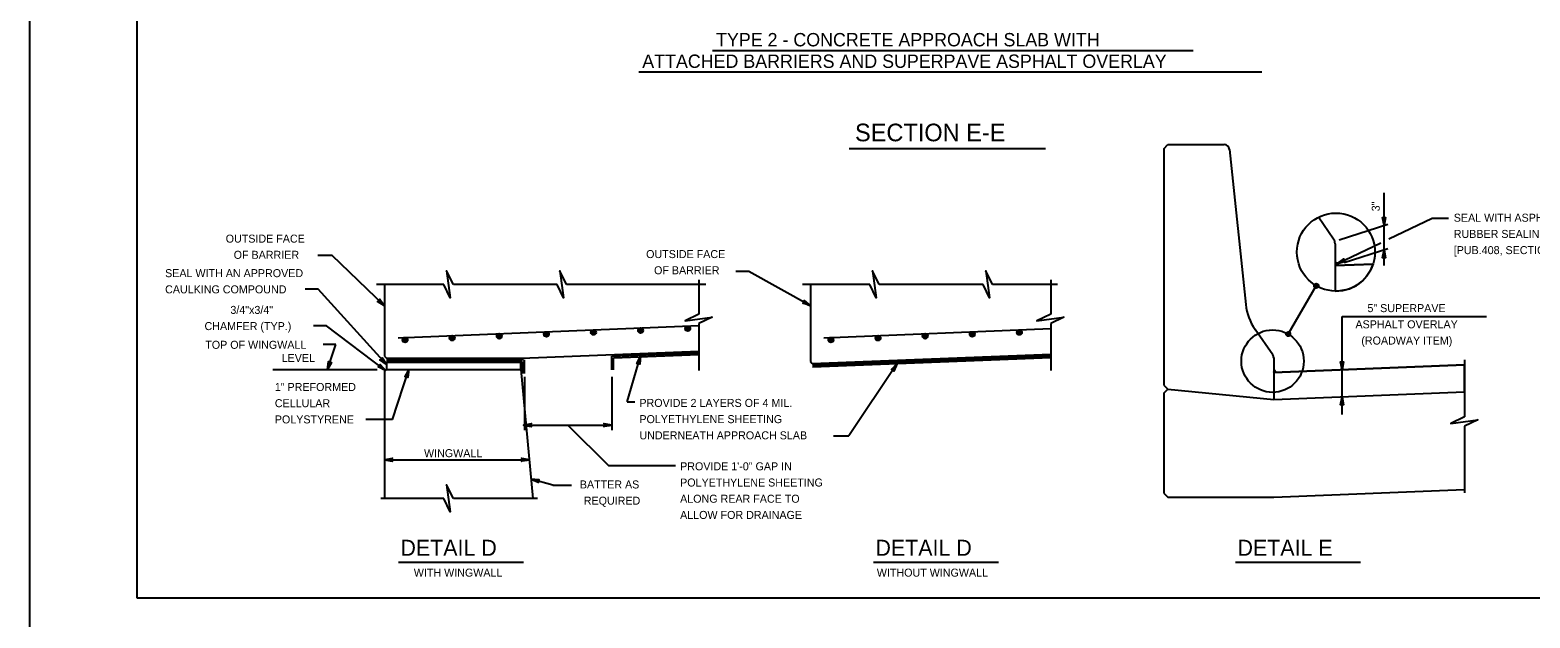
# Model space of a CAD drawing. Extents: x 636530 to 644067, y 294168 to 299122.
# Drawn here: x 638166 to 638728, y 297146 to 297366 of the extents above; entities that cross this region are included whole.
import ezdxf

# ---------------------------------------------------------------- set-up
doc = ezdxf.new("R2010")
doc.units = 0
doc.layers.add('1', color=7, linetype='Continuous')
doc.layers.add('PLT-BNDY', color=7, linetype='Continuous')

msp = doc.modelspace()

# ---------------------------------------------------------------- linework, layer by layer
at = {"layer": '1'}
for p, q in [((638205.78, 297717.48), (638205.78, 297153.48)), ((638421.64, 297358.59), (638601.78, 297358.59)), ((638393.93, 297350.66), (638627.46, 297350.66)), ((638472.78, 297321.93), (638546.37, 297321.93)), ((638590.8, 297321.82), (638592.32, 297323.35)), ((638590.8, 297321.82), (638590.8, 297233.27)), ((638592.32, 297323.35), (638613.36, 297323.35)), ((638615.38, 297321.53), (638621.5, 297263.45)), ((638673.29, 297278.03), (638673.29, 297305.33)), ((638654.39, 297287.97), (638648.7, 297296.14)), ((638656.53, 297287.69), (638674.72, 297293.57)), ((638675.11, 297288), (638691.29, 297295.75)), ((638691.29, 297295.75), (638697.47, 297295.75)), ((638654.94, 297286.22), (638654.94, 297268.45)), ((638655.83, 297278.75), (638672.05, 297286.53)), ((638279.01, 297281.84), (638273.63, 297281.84)), ((638298.63, 297262.95), (638279.01, 297281.84)), ((638658.37, 297279.14), (638674.72, 297284.42)), ((638435.25, 297275.84), (638430.38, 297275.84)), ((638458.27, 297262.95), (638435.25, 297275.84)), ((638654.94, 297278.04), (638669.21, 297278.61)), ((638273.74, 297269.19), (638268.87, 297269.19)), ((638299.39, 297240.9), (638273.74, 297269.19)), ((638320.95, 297270.92), (638295.64, 297270.92)), ((638298.63, 297270.92), (638298.63, 297244.08)), ((638363.41, 297270.92), (638324.47, 297270.92)), ((638419.05, 297270.92), (638366.93, 297270.92)), ((638416.49, 297272.73), (638416.49, 297259.8)), ((638480.6, 297270.92), (638455.29, 297270.92)), ((638458.27, 297270.92), (638458.27, 297242.02)), ((638523.06, 297270.92), (638484.12, 297270.92)), ((638550.92, 297270.92), (638526.57, 297270.92)), ((638548.35, 297272.73), (638548.35, 297259.8)), ((638637.38, 297252.34), (638647.92, 297270.44)), ((638657.56, 297222.25), (638657.56, 297258.96)), ((638657.56, 297258.96), (638711.74, 297258.96)), ((638276.86, 297255.42), (638271.99, 297255.42)), ((638299.04, 297238.72), (638276.86, 297255.42)), ((638303.73, 297251), (638416.49, 297255.51)), ((638416.49, 297256.28), (638416.49, 297238.65)), ((638463.38, 297251), (638548.35, 297254.4)), ((638548.35, 297256.28), (638548.35, 297238.65)), ((638631.58, 297244.62), (638624.99, 297254.09)), ((638280.36, 297248.46), (638275.73, 297248.46)), ((638277.29, 297239.07), (638280.36, 297248.46)), ((638350.06, 297243.32), (638416.49, 297245.98)), ((638298.63, 297244.08), (638299.39, 297243.32)), ((638299.39, 297243.32), (638350.06, 297243.32)), ((638350.81, 297242.68), (638299.39, 297242.68)), ((638350.18, 297242.05), (638299.39, 297242.05)), ((638350.34, 297237.63), (638350.34, 297242.05)), ((638351.11, 297237.63), (638351.11, 297242.68)), ((638383.88, 297244.04), (638416.49, 297245.34)), ((638383.88, 297238.98), (638383.88, 297244.04)), ((638384.51, 297243.43), (638416.49, 297244.71)), ((638384.51, 297238.98), (638384.51, 297243.43)), ((638389.59, 297226.92), (638394.62, 297244.06)), ((638458.27, 297242.02), (638459.01, 297241.29)), ((638459.01, 297241.29), (638548.35, 297244.86)), ((638459.03, 297240.66), (638548.35, 297244.23)), ((638459.06, 297240.02), (638548.35, 297243.6)), ((638490.76, 297241.29), (638472.74, 297214.18)), ((638631.95, 297243.46), (638631.95, 297227.83)), ((638631.95, 297238), (638703.47, 297240.86)), ((638703.47, 297242.73), (638703.47, 297221.38)), ((638703.47, 297230.7), (638703.47, 297240.86)), ((638256.85, 297239.07), (638295.91, 297239.07)), ((638298.63, 297238.31), (638299.39, 297239.07)), ((638298.63, 297238.31), (638298.63, 297190.69)), ((638299.39, 297239.07), (638349.78, 297239.07)), ((638301.68, 297220.35), (638307.8, 297239.07)), ((638349.78, 297239.07), (638354.24, 297190.69)), ((638351.11, 297236.38), (638351.11, 297216.41)), ((638383.88, 297236.38), (638383.88, 297216.41)), ((638590.8, 297233.27), (638592.32, 297231.75)), ((638590.8, 297230.22), (638592.32, 297231.75)), ((638590.8, 297230.22), (638590.8, 297192.75)), ((638592.32, 297231.75), (638631.95, 297227.83)), ((638631.95, 297227.83), (638703.47, 297230.69)), ((638389.59, 297226.92), (638392.46, 297226.92)), ((638301.68, 297220.35), (638291.66, 297220.35)), ((638350.81, 297218.23), (638383.88, 297218.23)), ((638367.34, 297218.23), (638382.64, 297203.17)), ((638703.47, 297217.86), (638703.47, 297192.83)), ((638466.97, 297214.18), (638472.74, 297214.18)), ((638298.63, 297205.27), (638353.02, 297205.27)), ((638382.64, 297203.17), (638407.72, 297203.17)), ((638361.75, 297195.78), (638353.63, 297198.05)), ((638361.75, 297195.78), (638368.73, 297195.78)), ((638320.95, 297190.69), (638297.29, 297190.69)), ((638356.03, 297190.69), (638324.47, 297190.69)), ((638590.8, 297192.75), (638592.32, 297191.23)), ((638592.32, 297191.23), (638631.95, 297191.23)), ((638631.95, 297191.23), (638703.47, 297194.09)), ((638303.9, 297166.88), (638350.7, 297166.88)), ((638481.94, 297166.88), (638528.75, 297166.88)), ((638617.62, 297166.88), (638664.43, 297166.88)), ((638205.78, 297153.48), (638991.78, 297153.48))]:
    msp.add_line(p, q, dxfattribs=at)
for points in [[(638673.29, 297293.1), (638672.73, 297296.09), (638672.89, 297295.86), (638673.09, 297295.74), (638673.29, 297295.7), (638673.49, 297295.74), (638673.69, 297295.86), (638673.84, 297296.09), (638673.29, 297293.1), (638673.69, 297295.86), (638673.49, 297295.74), (638673.29, 297293.1), (638673.29, 297295.7), (638673.09, 297295.74), (638673.29, 297293.1), (638672.89, 297295.86)], [(638655.83, 297278.75), (638658.28, 297280.55), (638658.14, 297280.3), (638658.12, 297280.07), (638658.18, 297279.88), (638658.29, 297279.71), (638658.49, 297279.58), (638658.76, 297279.54), (638655.83, 297278.75), (638658.49, 297279.58), (638658.29, 297279.71), (638655.83, 297278.75), (638658.18, 297279.88), (638658.12, 297280.07), (638655.83, 297278.75), (638658.14, 297280.3)], [(638673.29, 297283.96), (638673.84, 297280.98), (638673.69, 297281.21), (638673.49, 297281.33), (638673.29, 297281.36), (638673.09, 297281.33), (638672.89, 297281.21), (638672.73, 297280.98), (638673.29, 297283.96), (638672.89, 297281.21), (638673.09, 297281.33), (638673.29, 297283.96), (638673.29, 297281.36), (638673.49, 297281.33), (638673.29, 297283.96), (638673.69, 297281.21)], [(638324.47, 297270.92), (638321.93, 297276.11), (638323.31, 297265.96), (638320.95, 297270.92)], [(638366.93, 297270.92), (638364.39, 297276.11), (638365.77, 297265.96), (638363.41, 297270.92)], [(638484.12, 297270.92), (638481.58, 297276.11), (638482.96, 297265.96), (638480.6, 297270.92)], [(638526.57, 297270.92), (638524.04, 297276.11), (638525.42, 297265.96), (638523.06, 297270.92)], [(638654.94, 297268.45), (638657.87, 297268.68), (638660.35, 297269.35), (638662.94, 297270.61), (638665.05, 297272.19), (638666.9, 297274.18), (638668.32, 297276.43), (638669.21, 297278.61)], [(638669.21, 297278.61), (638654.94, 297278.04), (638654.94, 297268.45)], [(638298.63, 297262.95), (638296.09, 297264.62), (638296.37, 297264.57), (638296.59, 297264.64), (638296.76, 297264.76), (638296.87, 297264.92), (638296.92, 297265.15), (638296.87, 297265.42), (638298.63, 297262.95), (638296.92, 297265.15), (638296.87, 297264.92), (638298.63, 297262.95), (638296.76, 297264.76), (638296.59, 297264.64), (638298.63, 297262.95), (638296.37, 297264.57)], [(638458.27, 297262.95), (638455.4, 297263.92), (638455.68, 297263.95), (638455.88, 297264.07), (638456.01, 297264.22), (638456.07, 297264.41), (638456.07, 297264.65), (638455.94, 297264.9), (638458.27, 297262.95), (638456.07, 297264.65), (638456.07, 297264.41), (638458.27, 297262.95), (638456.01, 297264.22), (638455.88, 297264.07), (638458.27, 297262.95), (638455.68, 297263.95)], [(638416.49, 297259.8), (638411.3, 297257.26), (638421.45, 297258.64), (638416.49, 297256.28)], [(638548.35, 297259.8), (638543.17, 297257.26), (638553.32, 297258.64), (638548.35, 297256.28)], [(638277.29, 297239.07), (638277.69, 297242.08), (638277.73, 297241.94), (638277.77, 297241.81), (638277.84, 297241.72), (638277.92, 297241.64), (638278.01, 297241.59), (638278.1, 297241.54), (638278.2, 297241.53), (638278.3, 297241.51), (638278.41, 297241.54), (638278.53, 297241.56), (638278.64, 297241.65), (638278.75, 297241.73), (638277.29, 297239.07), (638278.64, 297241.65), (638278.53, 297241.56), (638277.29, 297239.07), (638278.41, 297241.54), (638278.3, 297241.51), (638277.29, 297239.07), (638278.2, 297241.53), (638278.1, 297241.54), (638277.29, 297239.07), (638278.01, 297241.59), (638277.92, 297241.64), (638277.29, 297239.07), (638277.84, 297241.72), (638277.77, 297241.81), (638277.29, 297239.07), (638277.73, 297241.94)], [(638299.04, 297238.72), (638296.32, 297240.06), (638296.46, 297240.06), (638296.6, 297240.05), (638296.71, 297240.1), (638296.81, 297240.14), (638296.89, 297240.21), (638296.96, 297240.28), (638297.01, 297240.37), (638297.05, 297240.46), (638297.07, 297240.58), (638297.08, 297240.69), (638297.04, 297240.82), (638296.99, 297240.96), (638299.04, 297238.72), (638297.04, 297240.82), (638297.08, 297240.69), (638299.04, 297238.72), (638297.07, 297240.58), (638297.05, 297240.46), (638299.04, 297238.72), (638297.01, 297240.37), (638296.96, 297240.28), (638299.04, 297238.72), (638296.89, 297240.21), (638296.81, 297240.14), (638299.04, 297238.72), (638296.71, 297240.1), (638296.6, 297240.05), (638299.04, 297238.72), (638296.46, 297240.06)], [(638299.39, 297240.9), (638296.97, 297242.73), (638297.11, 297242.7), (638297.25, 297242.67), (638297.36, 297242.69), (638297.47, 297242.72), (638297.56, 297242.77), (638297.64, 297242.82), (638297.71, 297242.9), (638297.77, 297242.98), (638297.8, 297243.1), (638297.84, 297243.21), (638297.82, 297243.35), (638297.8, 297243.48), (638299.39, 297240.9), (638297.82, 297243.35), (638297.84, 297243.21), (638299.39, 297240.9), (638297.8, 297243.1), (638297.77, 297242.98), (638299.39, 297240.9), (638297.71, 297242.9), (638297.64, 297242.82), (638299.39, 297240.9), (638297.56, 297242.77), (638297.47, 297242.72), (638299.39, 297240.9), (638297.36, 297242.69), (638297.25, 297242.67), (638299.39, 297240.9), (638297.11, 297242.7)], [(638394.62, 297244.06), (638394.31, 297241.04), (638394.23, 297241.3), (638394.07, 297241.47), (638393.88, 297241.56), (638393.68, 297241.59), (638393.46, 297241.53), (638393.24, 297241.35), (638394.62, 297244.06), (638393.46, 297241.53), (638393.68, 297241.59), (638394.62, 297244.06), (638393.88, 297241.56), (638394.07, 297241.47), (638394.62, 297244.06), (638394.23, 297241.3)], [(638490.76, 297241.29), (638489.57, 297238.5), (638489.57, 297238.78), (638489.46, 297238.99), (638489.32, 297239.13), (638489.13, 297239.21), (638488.9, 297239.22), (638488.64, 297239.12), (638490.76, 297241.29), (638488.9, 297239.22), (638489.13, 297239.21), (638490.76, 297241.29), (638489.32, 297239.13), (638489.46, 297238.99), (638490.76, 297241.29), (638489.57, 297238.78)], [(638703.47, 297240.86), (638631.95, 297238), (638631.95, 297227.84), (638703.47, 297230.7)], [(638657.56, 297239.03), (638657.01, 297242.01), (638657.08, 297241.89), (638657.16, 297241.78), (638657.26, 297241.72), (638657.36, 297241.66), (638657.46, 297241.64), (638657.56, 297241.63), (638657.66, 297241.64), (638657.76, 297241.66), (638657.86, 297241.72), (638657.96, 297241.78), (638658.04, 297241.89), (638658.12, 297242.01), (638657.56, 297239.03), (638658.04, 297241.89), (638657.96, 297241.78), (638657.56, 297239.03), (638657.86, 297241.72), (638657.76, 297241.66), (638657.56, 297239.03), (638657.66, 297241.64), (638657.56, 297241.63), (638657.56, 297239.03), (638657.46, 297241.64), (638657.36, 297241.66), (638657.56, 297239.03), (638657.26, 297241.72), (638657.16, 297241.78), (638657.56, 297239.03), (638657.08, 297241.89)], [(638307.8, 297239.07), (638306.34, 297236.41), (638306.46, 297236.49), (638306.57, 297236.58), (638306.68, 297236.6), (638306.79, 297236.63), (638306.89, 297236.61), (638307, 297236.6), (638307.08, 297236.55), (638307.17, 297236.5), (638307.25, 297236.42), (638307.33, 297236.33), (638307.37, 297236.19), (638307.41, 297236.06), (638307.8, 297239.07), (638307.37, 297236.19), (638307.33, 297236.33), (638307.8, 297239.07), (638307.25, 297236.42), (638307.17, 297236.5), (638307.8, 297239.07), (638307.08, 297236.55), (638307, 297236.6), (638307.8, 297239.07), (638306.89, 297236.61), (638306.79, 297236.63), (638307.8, 297239.07), (638306.68, 297236.6), (638306.57, 297236.58), (638307.8, 297239.07), (638306.46, 297236.49)], [(638657.56, 297228.86), (638658.12, 297225.87), (638658.04, 297225.99), (638657.96, 297226.1), (638657.86, 297226.16), (638657.76, 297226.22), (638657.66, 297226.24), (638657.56, 297226.26), (638657.46, 297226.24), (638657.36, 297226.22), (638657.26, 297226.16), (638657.16, 297226.1), (638657.08, 297225.99), (638657.01, 297225.87), (638657.56, 297228.86), (638657.08, 297225.99), (638657.16, 297226.1), (638657.56, 297228.86), (638657.26, 297226.16), (638657.36, 297226.22), (638657.56, 297228.86), (638657.46, 297226.24), (638657.56, 297226.26), (638657.56, 297228.86), (638657.66, 297226.24), (638657.76, 297226.22), (638657.56, 297228.86), (638657.86, 297226.16), (638657.96, 297226.1), (638657.56, 297228.86), (638658.04, 297225.99)], [(638350.81, 297218.23), (638353.79, 297218.79), (638353.68, 297218.71), (638353.56, 297218.63), (638353.5, 297218.53), (638353.44, 297218.43), (638353.43, 297218.33), (638353.41, 297218.23), (638353.43, 297218.13), (638353.44, 297218.03), (638353.5, 297217.93), (638353.56, 297217.83), (638353.68, 297217.75), (638353.79, 297217.67), (638350.81, 297218.23), (638353.68, 297217.75), (638353.56, 297217.83), (638350.81, 297218.23), (638353.5, 297217.93), (638353.44, 297218.03), (638350.81, 297218.23), (638353.43, 297218.13), (638353.41, 297218.23), (638350.81, 297218.23), (638353.43, 297218.33), (638353.44, 297218.43), (638350.81, 297218.23), (638353.5, 297218.53), (638353.56, 297218.63), (638350.81, 297218.23), (638353.68, 297218.71)], [(638383.88, 297218.23), (638380.9, 297217.67), (638381.01, 297217.75), (638381.13, 297217.83), (638381.19, 297217.93), (638381.24, 297218.03), (638381.26, 297218.13), (638381.28, 297218.23), (638381.26, 297218.33), (638381.24, 297218.43), (638381.19, 297218.53), (638381.13, 297218.63), (638381.01, 297218.71), (638380.9, 297218.79), (638383.88, 297218.23), (638381.01, 297218.71), (638381.13, 297218.63), (638383.88, 297218.23), (638381.19, 297218.53), (638381.24, 297218.43), (638383.88, 297218.23), (638381.26, 297218.33), (638381.28, 297218.23), (638383.88, 297218.23), (638381.26, 297218.13), (638381.24, 297218.03), (638383.88, 297218.23), (638381.19, 297217.93), (638381.13, 297217.83), (638383.88, 297218.23), (638381.01, 297217.75)], [(638703.47, 297221.38), (638698.29, 297218.84), (638708.43, 297220.22), (638703.47, 297217.86)], [(638298.63, 297205.27), (638301.61, 297205.83), (638301.5, 297205.75), (638301.38, 297205.67), (638301.32, 297205.57), (638301.26, 297205.47), (638301.25, 297205.37), (638301.23, 297205.27), (638301.25, 297205.17), (638301.26, 297205.07), (638301.32, 297204.97), (638301.38, 297204.87), (638301.5, 297204.79), (638301.61, 297204.71), (638298.63, 297205.27), (638301.5, 297204.79), (638301.38, 297204.87), (638298.63, 297205.27), (638301.32, 297204.97), (638301.26, 297205.07), (638298.63, 297205.27), (638301.25, 297205.17), (638301.23, 297205.27), (638298.63, 297205.27), (638301.25, 297205.37), (638301.26, 297205.47), (638298.63, 297205.27), (638301.32, 297205.57), (638301.38, 297205.67), (638298.63, 297205.27), (638301.5, 297205.75)], [(638353.02, 297205.27), (638350.04, 297204.71), (638350.16, 297204.79), (638350.27, 297204.87), (638350.33, 297204.97), (638350.39, 297205.07), (638350.41, 297205.17), (638350.42, 297205.27), (638350.41, 297205.37), (638350.39, 297205.47), (638350.33, 297205.57), (638350.27, 297205.67), (638350.16, 297205.75), (638350.04, 297205.83), (638353.02, 297205.27), (638350.16, 297205.75), (638350.27, 297205.67), (638353.02, 297205.27), (638350.33, 297205.57), (638350.39, 297205.47), (638353.02, 297205.27), (638350.41, 297205.37), (638350.42, 297205.27), (638353.02, 297205.27), (638350.41, 297205.17), (638350.39, 297205.07), (638353.02, 297205.27), (638350.33, 297204.97), (638350.27, 297204.87), (638353.02, 297205.27), (638350.16, 297204.79)], [(638324.47, 297190.69), (638321.93, 297195.88), (638323.31, 297185.73), (638320.95, 297190.69)], [(638353.63, 297198.05), (638356.65, 297197.79), (638356.52, 297197.74), (638356.38, 297197.7), (638356.3, 297197.61), (638356.22, 297197.53), (638356.17, 297197.44), (638356.13, 297197.35), (638356.12, 297197.25), (638356.11, 297197.15), (638356.14, 297197.04), (638356.17, 297196.92), (638356.26, 297196.82), (638356.35, 297196.71), (638353.63, 297198.05), (638356.26, 297196.82), (638356.17, 297196.92), (638353.63, 297198.05), (638356.14, 297197.04), (638356.11, 297197.15), (638353.63, 297198.05), (638356.12, 297197.25), (638356.13, 297197.35), (638353.63, 297198.05), (638356.17, 297197.44), (638356.22, 297197.53), (638353.63, 297198.05), (638356.3, 297197.61), (638356.38, 297197.7), (638353.63, 297198.05), (638356.52, 297197.74)]]:
    msp.add_lwpolyline(points, dxfattribs=at)
msp.add_lwpolyline([(638299.39, 297239.07), (638349.78, 297239.07), (638349.78, 297241.67), (638299.39, 297241.67)], close=True, dxfattribs=at)
for centre, radius in [((638655.28, 297283.08), 14.63), ((638647.92, 297270.44), 0.834), ((638306.35, 297250.15), 0.952), ((638324.01, 297250.86), 0.952), ((638324.01, 297250.86), 0.714), ((638324.01, 297250.86), 0.476), ((638324.01, 297250.86), 0.238), ((638341.67, 297251.56), 0.952), ((638341.67, 297251.56), 0.714), ((638341.67, 297251.56), 0.476), ((638341.67, 297251.56), 0.238), ((638359.33, 297252.27), 0.952), ((638359.33, 297252.27), 0.714), ((638359.33, 297252.27), 0.476), ((638359.33, 297252.27), 0.238), ((638376.99, 297252.98), 0.952), ((638376.99, 297252.98), 0.714), ((638376.99, 297252.98), 0.476), ((638376.99, 297252.98), 0.238), ((638394.65, 297253.68), 0.952), ((638394.65, 297253.68), 0.714), ((638394.65, 297253.68), 0.476), ((638394.65, 297253.68), 0.238), ((638412.31, 297254.39), 0.952), ((638412.31, 297254.39), 0.714), ((638412.31, 297254.39), 0.476), ((638412.31, 297254.39), 0.238), ((638466, 297250.15), 0.952), ((638483.66, 297250.86), 0.952), ((638483.66, 297250.86), 0.714), ((638483.66, 297250.86), 0.476), ((638483.66, 297250.86), 0.238), ((638501.32, 297251.56), 0.952), ((638501.32, 297251.56), 0.714), ((638501.32, 297251.56), 0.476), ((638501.32, 297251.56), 0.238), ((638518.98, 297252.27), 0.952), ((638518.98, 297252.27), 0.714), ((638518.98, 297252.27), 0.476), ((638518.98, 297252.27), 0.238), ((638536.64, 297252.98), 0.952), ((638536.64, 297252.98), 0.714), ((638536.64, 297252.98), 0.476), ((638536.64, 297252.98), 0.238), ((638631.52, 297242.21), 11.7), ((638637.38, 297252.34), 0.8), ((638306.35, 297250.15), 0.714), ((638306.35, 297250.15), 0.476), ((638306.35, 297250.15), 0.238), ((638466, 297250.15), 0.714), ((638466, 297250.15), 0.476), ((638466, 297250.15), 0.238)]:
    msp.add_circle(centre, radius, dxfattribs=at)
for centre, radius, start, end in [((638613.36, 297321.31), 2.03, 6.0195, 90), ((638651.89, 297286.22), 3.05, 0, 34.8593), ((638651.89, 297286.22), 3.05, 0, 34.8593), ((638651.89, 297286.22), 3.05, 0, 34.8593), ((638654.94, 297278.04), 1.14, 2.2906, 90), ((638654.94, 297278.04), 0.962, 2.2906, 90), ((638654.94, 297278.04), 0.779, 2.2906, 90), ((638654.94, 297278.04), 0.596, 2.2906, 90), ((638654.94, 297278.04), 0.413, 2.2906, 90), ((638654.94, 297278.04), 0.23, 2.2906, 90), ((638641.45, 297265.56), 20.07, 186.0195, 214.8593), ((638629.92, 297243.46), 2.03, 0, 34.8593), ((638629.92, 297243.46), 2.03, 0, 34.8593), ((638629.92, 297243.46), 2.03, 0, 34.8593), ((638629.92, 297243.46), 2.03, 0, 34.8593), ((638629.92, 297243.46), 2.03, 0, 34.8593), ((638631.95, 297238), 0.763, 2.2906, 90), ((638631.95, 297238), 0.641, 2.2906, 90), ((638631.95, 297238), 0.519, 2.2906, 90), ((638631.95, 297238), 0.397, 2.2906, 90), ((638631.95, 297238), 0.276, 2.2906, 90), ((638631.95, 297238), 0.154, 2.2906, 90)]:
    msp.add_arc(centre, radius, start, end, dxfattribs=at)
at = {"layer": 'PLT-BNDY'}
msp.add_lwpolyline([(638165.78, 297732.48), (639006.78, 297732.48), (639006.78, 297138.48), (638165.78, 297138.48)], close=True, dxfattribs=at)

# ---------------------------------------------------------------- texts
at = {"layer": '1'}
for s, height, p in [('TYPE 2 - CONCRETE APPROACH SLAB WITH', 5, (638422.93, 297360.16)), ('ATTACHED BARRIERS AND SUPERPAVE ASPHALT OVERLAY', 5, (638395.27, 297352.09)), ('SECTION E-E', 6.6, (638475.01, 297324.59)), ('SEAL WITH ASPHALT', 3, (638699.44, 297294.45)), ('RUBBER SEALING COMPOUND', 3, (638699.44, 297288.38)), ('OUTSIDE FACE', 3, (638239.14, 297286.62)), ('[PUB.408, SECTION 705.4(g)]', 3, (638699.44, 297282.31)), ('OF BARRIER', 3, (638242.13, 297280.55)), ('OUTSIDE FACE', 3, (638396.72, 297280.83)), ('SEAL WITH AN APPROVED', 3, (638216.43, 297273.68)), ('OF BARRIER', 3, (638399.7, 297274.76)), ('CAULKING COMPOUND', 3, (638216.43, 297267.61)), ('3/4"x3/4"', 3, (638240.89, 297259.91)), ('5" SUPERPAVE', 3, (638667.08, 297260.58)), ('CHAMFER (TYP.)', 3, (638231.2, 297253.84)), ('ASPHALT OVERLAY', 3, (638662.59, 297254.51)), ('(ROADWAY ITEM)', 3, (638664.79, 297248.43)), ('TOP OF WINGWALL', 3, (638231.48, 297246.84)), ('LEVEL', 3, (638260.11, 297241.89)), ('1" PREFORMED', 3, (638257.55, 297231.02)), ('CELLULAR ', 3, (638257.55, 297224.95)), ('PROVIDE 2 LAYERS OF 4 MIL.', 3, (638394.2, 297225.06)), ('POLYSTYRENE', 3, (638257.55, 297218.88)), ('POLYETHYLENE SHEETING', 3, (638394.2, 297218.98)), ('UNDERNEATH APPROACH SLAB', 3, (638394.2, 297212.91)), ('WINGWALL', 3, (638313.47, 297206.23)), ('PROVIDE 1\'-0" GAP IN', 3, (638409.46, 297201.31)), ('BATTER AS', 3, (638371.87, 297194.51)), ('POLYETHYLENE SHEETING', 3, (638409.46, 297195.24)), ('REQUIRED', 3, (638373.36, 297188.43)), ('ALONG REAR FACE TO', 3, (638409.46, 297189.16)), ('ALLOW FOR DRAINAGE', 3, (638409.46, 297183.09)), ('DETAIL D', 6, (638304.63, 297169.29)), ('DETAIL D', 6, (638482.67, 297169.29)), ('DETAIL E', 6, (638618.38, 297169.29)), ('WITH WINGWALL', 3, (638309.64, 297161.47)), ('WITHOUT WINGWALL', 3, (638483.19, 297161.47))]:
    msp.add_text(s, height=height, dxfattribs=at).set_placement(p)
msp.add_text('3"', height=3, rotation=90, dxfattribs=at).set_placement((638671.69, 297298.35))

doc.saveas('drawing.dxf')
